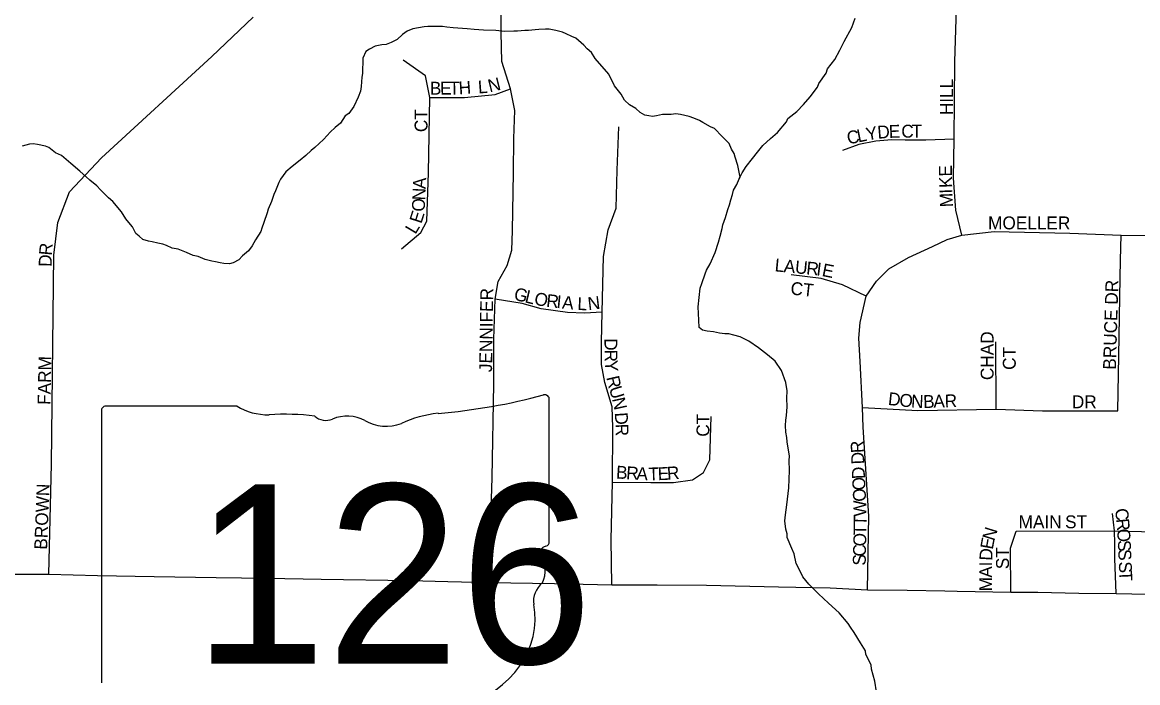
# Model space of a CAD drawing. Extents: x 0 to 34, y -2.3 to 22.
# Drawn here: x 4.399 to 5.22, y 14.899 to 15.385 of the extents above; entities that cross this region are included whole.
import ezdxf

# ---------------------------------------------------------------- set-up
doc = ezdxf.new("R2010")
doc.units = 0
for name, color, linetype in [('GM_X_Minor_River', 7, 'Continuous'), ('GM_X_State_Location', 7, 'Continuous'), ('GM_X_State_Route', 7, 'Continuous'), ('GM_X_State_Shield', 7, 'Continuous'), ('GM_X_Township_Subdivision', 7, 'Continuous'), ('GM_X_Township_Subdivision_Text', 7, 'Continuous')]:
    doc.layers.add(name, color=color, linetype=linetype)

msp = doc.modelspace()

# ---------------------------------------------------------------- linework, layer by layer
at = {"layer": 'GM_X_Minor_River'}
for p, q in [((5.00937, 15.38162), (5.01185, 15.38839)), ((4.67853, 15.37632), (4.67462, 15.37264)), ((4.68202, 15.37887), (4.67853, 15.37632)), ((4.68626, 15.38065), (4.68202, 15.37887)), ((4.69465, 15.38192), (4.68626, 15.38065)), ((4.69732, 15.38222), (4.69465, 15.38192)), ((4.70797, 15.38228), (4.69732, 15.38222)), ((4.71138, 15.3818), (4.70797, 15.38228)), ((4.71592, 15.38128), (4.71138, 15.3818)), ((4.72617, 15.3806), (4.71592, 15.38128)), ((4.73147, 15.38006), (4.72617, 15.3806)), ((4.7383, 15.37947), (4.73147, 15.38006)), ((4.74741, 15.3792), (4.7383, 15.37947)), ((4.75386, 15.37863), (4.74741, 15.3792)), ((4.7607, 15.3788), (4.75386, 15.37863)), ((4.76336, 15.37872), (4.7607, 15.3788)), ((4.7687, 15.37932), (4.76336, 15.37872)), ((4.77136, 15.37924), (4.7687, 15.37932)), ((4.77632, 15.37985), (4.77136, 15.37924)), ((4.77899, 15.38016), (4.77632, 15.37985)), ((4.78393, 15.38039), (4.77899, 15.38016)), ((4.78659, 15.38031), (4.78393, 15.38039)), ((4.79151, 15.3794), (4.78659, 15.38031)), ((4.79641, 15.37811), (4.79151, 15.3794)), ((4.79904, 15.3769), (4.79641, 15.37811)), ((4.80316, 15.37487), (4.79904, 15.3769)), ((5.00375, 15.37115), (5.00937, 15.38162)), ((4.66349, 15.36879), (4.65852, 15.3678)), ((4.66654, 15.36908), (4.66349, 15.36879)), ((4.67038, 15.37049), (4.66654, 15.36908)), ((4.67462, 15.37264), (4.67038, 15.37049)), ((4.80617, 15.37364), (4.80316, 15.37487)), ((4.8121, 15.36853), (4.80617, 15.37364)), ((4.81468, 15.36579), (4.8121, 15.36853)), ((5.00052, 15.36479), (5.00375, 15.37115)), ((4.65156, 15.36383), (4.64952, 15.35895)), ((4.65427, 15.36565), (4.65156, 15.36383)), ((4.65852, 15.3678), (4.65427, 15.36565)), ((4.81764, 15.36304), (4.81468, 15.36579)), ((4.82056, 15.35878), (4.81764, 15.36304)), ((4.99691, 15.35806), (5.00052, 15.36479)), ((4.64952, 15.35895), (4.64919, 15.34756)), ((4.83049, 15.34708), (4.82056, 15.35878)), ((4.99138, 15.35101), (4.99691, 15.35806)), ((4.64873, 15.34492), (4.64816, 15.3381)), ((4.64919, 15.34756), (4.64873, 15.34492)), ((4.8348, 15.3386), (4.83049, 15.34708)), ((4.98499, 15.34018), (4.99053, 15.348)), ((4.99053, 15.348), (4.99138, 15.35101)), ((4.64816, 15.3381), (4.64768, 15.33469)), ((4.83956, 15.33237), (4.8348, 15.3386)), ((4.97863, 15.3305), (4.98415, 15.33755)), ((4.98415, 15.33755), (4.98499, 15.34018)), ((4.64603, 15.33018), (4.64279, 15.32344)), ((4.64768, 15.33469), (4.64603, 15.33018)), ((4.8421, 15.32812), (4.83956, 15.33237)), ((4.8458, 15.32459), (4.8421, 15.32812)), ((4.9739, 15.32494), (4.97863, 15.3305)), ((4.64279, 15.32344), (4.63922, 15.31823)), ((4.85028, 15.3218), (4.8458, 15.32459)), ((4.85362, 15.31904), (4.85028, 15.3218)), ((4.85699, 15.31704), (4.85362, 15.31904)), ((4.9622, 15.31465), (4.96881, 15.31977)), ((4.96881, 15.31977), (4.9739, 15.32494)), ((4.63294, 15.3112), (4.62904, 15.30789)), ((4.63651, 15.31641), (4.63294, 15.3112)), ((4.63922, 15.31823), (4.63651, 15.31641)), ((4.86001, 15.31657), (4.85699, 15.31704)), ((4.86266, 15.31611), (4.86001, 15.31657)), ((4.86571, 15.3164), (4.86266, 15.31611)), ((4.86992, 15.31741), (4.86571, 15.3164)), ((4.87639, 15.3176), (4.86992, 15.31741)), ((4.87982, 15.31787), (4.87639, 15.3176)), ((4.88322, 15.31739), (4.87982, 15.31787)), ((4.88964, 15.31606), (4.88322, 15.31739)), ((4.89303, 15.31482), (4.88964, 15.31606)), ((4.89717, 15.31317), (4.89303, 15.31482)), ((4.89978, 15.31158), (4.89717, 15.31317)), ((4.90539, 15.30837), (4.89978, 15.31158)), ((4.95468, 15.30424), (4.96137, 15.31202)), ((4.96137, 15.31202), (4.9622, 15.31465)), ((4.62552, 15.30458), (4.62317, 15.30199)), ((4.62904, 15.30789), (4.62552, 15.30458)), ((4.90839, 15.30714), (4.90539, 15.30837)), ((4.91393, 15.30128), (4.90839, 15.30714)), ((4.94961, 15.29983), (4.95468, 15.30424)), ((4.40404, 15.29562), (4.39868, 15.29426)), ((4.40671, 15.29592), (4.40404, 15.29562)), ((4.41012, 15.29544), (4.40671, 15.29592)), ((4.41578, 15.29413), (4.41012, 15.29544)), ((4.41842, 15.29329), (4.41578, 15.29413)), ((4.62042, 15.29903), (4.61417, 15.29314)), ((4.62317, 15.30199), (4.62042, 15.29903)), ((4.9191, 15.29618), (4.91393, 15.30128)), ((4.92088, 15.29195), (4.9191, 15.29618)), ((4.93982, 15.28987), (4.94376, 15.29469)), ((4.94376, 15.29469), (4.94961, 15.29983)), ((4.42325, 15.28935), (4.41842, 15.29329)), ((4.42775, 15.28732), (4.42325, 15.28935)), ((4.43442, 15.28142), (4.42775, 15.28732)), ((4.60754, 15.28726), (4.60326, 15.28397)), ((4.61145, 15.29094), (4.60754, 15.28726)), ((4.61417, 15.29314), (4.61145, 15.29094)), ((4.92269, 15.28886), (4.92088, 15.29195)), ((4.92337, 15.28618), (4.92269, 15.28886)), ((4.92548, 15.28004), (4.92337, 15.28618)), ((4.93626, 15.28503), (4.93982, 15.28987)), ((4.44111, 15.2759), (4.43442, 15.28142)), ((4.59742, 15.27921), (4.59275, 15.27517)), ((4.60326, 15.28397), (4.59742, 15.27921)), ((4.92613, 15.27622), (4.92548, 15.28004)), ((4.92874, 15.27462), (4.93153, 15.2791)), ((4.93153, 15.2791), (4.93626, 15.28503)), ((4.44592, 15.27158), (4.44111, 15.2759)), ((4.44851, 15.26922), (4.44592, 15.27158)), ((4.58879, 15.26997), (4.58758, 15.26734)), ((4.59275, 15.27517), (4.58879, 15.26997)), ((4.92469, 15.266), (4.92633, 15.27013)), ((4.92712, 15.27125), (4.92613, 15.27622)), ((4.92633, 15.27013), (4.92874, 15.27462)), ((4.92633, 15.27013), (4.92712, 15.27125)), ((4.45371, 15.26489), (4.44851, 15.26922)), ((4.45629, 15.26215), (4.45371, 15.26489)), ((4.46221, 15.25627), (4.45629, 15.26215)), ((4.58512, 15.26134), (4.58391, 15.25871)), ((4.58758, 15.26734), (4.58512, 15.26134)), ((4.92143, 15.2585), (4.92229, 15.2619)), ((4.92229, 15.2619), (4.92469, 15.266)), ((4.46555, 15.25351), (4.46221, 15.25627)), ((4.47178, 15.24573), (4.46555, 15.25351)), ((4.58224, 15.25345), (4.57979, 15.24782)), ((4.58391, 15.25871), (4.58224, 15.25345)), ((4.91932, 15.25097), (4.92018, 15.25474)), ((4.92018, 15.25474), (4.92143, 15.2585)), ((4.47506, 15.24069), (4.47178, 15.24573)), ((4.57896, 15.24519), (4.57647, 15.23804)), ((4.57979, 15.24782), (4.57896, 15.24519)), ((4.91638, 15.24156), (4.91808, 15.24759)), ((4.91808, 15.24759), (4.91932, 15.25097)), ((4.47726, 15.23797), (4.47506, 15.24069)), ((4.47983, 15.23485), (4.47726, 15.23797)), ((4.57647, 15.23804), (4.57521, 15.2339)), ((4.91433, 15.2363), (4.91638, 15.24156)), ((4.48235, 15.22984), (4.47983, 15.23485)), ((4.48495, 15.22786), (4.48235, 15.22984)), ((4.57437, 15.23127), (4.5704, 15.22531)), ((4.57521, 15.2339), (4.57437, 15.23127)), ((4.91257, 15.228), (4.91387, 15.23365)), ((4.91387, 15.23365), (4.91433, 15.2363)), ((4.48754, 15.2255), (4.48495, 15.22786)), ((4.49169, 15.22424), (4.48754, 15.2255)), ((4.49434, 15.22378), (4.49169, 15.22424)), ((4.49849, 15.2229), (4.49434, 15.22378)), ((4.50227, 15.22203), (4.49849, 15.2229)), ((4.5049, 15.22119), (4.50227, 15.22203)), ((4.50903, 15.21916), (4.5049, 15.22119)), ((4.56799, 15.22082), (4.56522, 15.2171)), ((4.5704, 15.22531), (4.56799, 15.22082)), ((4.9088, 15.21595), (4.9113, 15.22347)), ((4.9113, 15.22347), (4.91257, 15.228)), ((4.51356, 15.21827), (4.50903, 15.21916)), ((4.51957, 15.21581), (4.51356, 15.21827)), ((4.52445, 15.21376), (4.51957, 15.21581)), ((4.52823, 15.21289), (4.52445, 15.21376)), ((4.53349, 15.21083), (4.52823, 15.21289)), ((4.56094, 15.21343), (4.55819, 15.21048)), ((4.56522, 15.2171), (4.56094, 15.21343)), ((4.90514, 15.2077), (4.9088, 15.21595)), ((4.5384, 15.20955), (4.53349, 15.21083)), ((4.54104, 15.20909), (4.5384, 15.20955)), ((4.54444, 15.20823), (4.54104, 15.20909)), ((4.54709, 15.20777), (4.54444, 15.20823)), ((4.55127, 15.20764), (4.54709, 15.20777)), ((4.55395, 15.20832), (4.55127, 15.20764)), ((4.55819, 15.21048), (4.55395, 15.20832)), ((4.90234, 15.20285), (4.90514, 15.2077)), ((4.89902, 15.19307), (4.90151, 15.20021)), ((4.90151, 15.20021), (4.90234, 15.20285)), ((4.89625, 15.17605), (4.89778, 15.18968)), ((4.89778, 15.18968), (4.89902, 15.19307)), ((4.89672, 15.16616), (4.89625, 15.17605)), ((4.89695, 15.16084), (4.89672, 15.16616)), ((4.89955, 15.15886), (4.89695, 15.16084)), ((4.90295, 15.158), (4.89955, 15.15886)), ((4.9075, 15.15748), (4.90295, 15.158)), ((4.91203, 15.15659), (4.9075, 15.15748)), ((4.91582, 15.15609), (4.91203, 15.15659)), ((4.91886, 15.156), (4.91582, 15.15609)), ((4.92263, 15.15513), (4.91886, 15.156)), ((4.92716, 15.15385), (4.92263, 15.15513)), ((4.93353, 15.15063), (4.92716, 15.15385)), ((4.94061, 15.14585), (4.93353, 15.15063)), ((4.9473, 15.14071), (4.94061, 15.14585)), ((4.95287, 15.13599), (4.9473, 15.14071)), ((4.95761, 15.12901), (4.95287, 15.13599)), ((4.96077, 15.12018), (4.95761, 15.12901)), ((4.96174, 15.11407), (4.96077, 15.12018)), ((4.96159, 15.10875), (4.96174, 15.11407)), ((4.96178, 15.10229), (4.96159, 15.10875)), ((4.96121, 15.09585), (4.96178, 15.10229)), ((4.96063, 15.08865), (4.96074, 15.09244)), ((4.96074, 15.09244), (4.96121, 15.09585)), ((4.96086, 15.0837), (4.96063, 15.08865)), ((4.96151, 15.07988), (4.96086, 15.0837)), ((4.96179, 15.07646), (4.96151, 15.07988)), ((4.9634, 15.06615), (4.96179, 15.07646)), ((4.9633, 15.06273), (4.9634, 15.06615)), ((4.96347, 15.05551), (4.9633, 15.06273)), ((4.9631, 15.0426), (4.96347, 15.05551)), ((4.9621, 15.03427), (4.9631, 15.0426)), ((4.9616, 15.03011), (4.9621, 15.03427)), ((4.96063, 15.02292), (4.9616, 15.03011)), ((4.96012, 15.01838), (4.96063, 15.02292)), ((4.96071, 15.01228), (4.96012, 15.01838)), ((4.96175, 15.00883), (4.96071, 15.01228)), ((4.96167, 15.00617), (4.96175, 15.00883)), ((4.96524, 14.99809), (4.96167, 15.00617)), ((4.96703, 14.99424), (4.96524, 14.99809)), ((4.96834, 14.98698), (4.96703, 14.99424)), ((4.97086, 14.98234), (4.96834, 14.98698)), ((4.97338, 14.97733), (4.97086, 14.98234)), ((4.97778, 14.97188), (4.97338, 14.97733)), ((4.9848, 14.96483), (4.97778, 14.97188)), ((4.9922, 14.95777), (4.9848, 14.96483)), ((4.99998, 14.9507), (4.9922, 14.95777)), ((5.0066, 14.9429), (4.99998, 14.9507)), ((5.00842, 14.94019), (5.0066, 14.9429)), ((5.01097, 14.93631), (5.00842, 14.94019)), ((5.01569, 14.92857), (5.01097, 14.93631)), ((5.01932, 14.92277), (5.01569, 14.92857)), ((5.01962, 14.9201), (5.01932, 14.92277)), ((5.02358, 14.91238), (5.01962, 14.9201)), ((5.02388, 14.90933), (5.02358, 14.91238)), ((5.02628, 14.90052), (5.02388, 14.90933)), ((5.02757, 14.89251), (5.02628, 14.90052))]:
    msp.add_line(p, q, dxfattribs=at)
at = {"layer": 'GM_X_State_Route'}
for p, q in [((4.37638, 14.97924), (4.41835, 14.97924)), ((4.41835, 14.97924), (4.45408, 14.97808)), ((4.45408, 14.97808), (4.49589, 14.97758)), ((4.49589, 14.97758), (4.54158, 14.97668)), ((4.54158, 14.97668), (4.57872, 14.97629)), ((4.57872, 14.97629), (4.61874, 14.9756)), ((4.61874, 14.9756), (4.68439, 14.9746)), ((4.68439, 14.9746), (4.71191, 14.97381)), ((4.71191, 14.97381), (4.7421, 14.97301)), ((4.7421, 14.97301), (4.79056, 14.97232)), ((4.79056, 14.97232), (4.83277, 14.97142)), ((4.83277, 14.97142), (4.86614, 14.97142)), ((4.86614, 14.97142), (4.90249, 14.97102)), ((4.90249, 14.97102), (4.95533, 14.96984)), ((4.95533, 14.96984), (4.99346, 14.96924)), ((4.99346, 14.96924), (5.02088, 14.96765)), ((5.02088, 14.96765), (5.05007, 14.96737)), ((5.05007, 14.96737), (5.07778, 14.96689)), ((5.07778, 14.96689), (5.08696, 14.96674)), ((5.08696, 14.96674), (5.12638, 14.96584)), ((5.12638, 14.96584), (5.14634, 14.96603)), ((5.14634, 14.96603), (5.1764, 14.96522)), ((5.1764, 14.96522), (5.20381, 14.96496)), ((5.20381, 14.96496), (5.24073, 14.96426))]:
    msp.add_line(p, q, dxfattribs=at)
at = {"layer": 'GM_X_State_Shield'}
for p, q in [((4.78666, 15.00315), (4.78666, 15.10784)), ((4.45708, 15.09944), (4.45708, 14.89932)), ((4.55684, 15.10288), (4.46032, 15.10288)), ((4.78663, 15.00318), (4.78666, 15.00315))]:
    msp.add_line(p, q, dxfattribs=at)
for centre, major_axis, start_param, end_param in [((4.66926, 15.37571), (0.34952, 0), 4.814394, 5.042369), ((4.78301, 15.10827), (0.00367, 0), 6.141152, 7.989035), ((4.46085, 15.09986), (0.00382, 0), 1.712693, 3.28349), ((4.57983, 15.12611), (0.03703, 0), 4.042523, 4.731795), ((4.59211, 14.99053), (0.13295, 0), 1.404758, 1.657858), ((4.71384, 15.04176), (0.07032, 0), 1.699011, 2.107814), ((4.62229, 15.1009), (0.01068, 0), 3.836095, 5.185415), ((4.63798, 15.07777), (0.02221, 0), 0.950623, 2.079405), ((4.66665, 15.10949), (0.02672, 0), 4.081561, 5.145723), ((4.78581, 14.99547), (0.00568, 0), 1.883978, 3.671073), ((4.78275, 15.00275), (0.00393, 0), 5.05454, 6.418171), ((4.74969, 14.98224), (0.03409, 0), 5.934695, 6.695948), ((4.79981, 14.95934), (0.0248, 0), 2.387724, 3.262537), ((4.68884, 14.94603), (0.08742, 0), 5.101752, 6.440018)]:
    msp.add_ellipse(centre, major_axis=major_axis, ratio=0.8, start_param=start_param, end_param=end_param, dxfattribs=at)
at = {"layer": 'GM_X_Township_Subdivision'}
for p, q in [((4.75137, 15.37776), (4.75152, 15.42061)), ((5.08521, 15.35629), (5.08657, 15.40379)), ((4.53826, 15.36006), (4.56871, 15.38911)), ((4.75165, 15.35641), (4.75137, 15.37776)), ((4.45702, 15.28559), (4.53826, 15.36006)), ((4.69564, 15.34585), (4.67923, 15.35742)), ((4.75822, 15.33626), (4.75165, 15.35641)), ((5.08458, 15.29926), (5.08521, 15.35629)), ((4.69884, 15.33001), (4.69564, 15.34585)), ((4.74673, 15.33219), (4.75822, 15.33626)), ((4.76142, 15.32041), (4.75822, 15.33626)), ((4.69766, 15.27443), (4.69884, 15.33001)), ((4.69884, 15.33001), (4.72427, 15.33)), ((4.72427, 15.33), (4.74673, 15.33219)), ((4.76059, 15.29975), (4.76142, 15.32041)), ((4.83671, 15.27653), (4.83794, 15.30838)), ((4.76031, 15.27477), (4.76059, 15.29975)), ((5.01441, 15.29529), (5.0024, 15.29105)), ((5.02699, 15.29798), (5.01441, 15.29529)), ((5.03871, 15.29883), (5.02699, 15.29798)), ((5.04861, 15.29854), (5.03871, 15.29883)), ((5.06387, 15.29868), (5.04861, 15.29854)), ((5.08458, 15.29926), (5.06387, 15.29868)), ((5.08426, 15.27075), (5.08458, 15.29926)), ((4.43356, 15.26066), (4.45702, 15.28559)), ((4.69648, 15.23888), (4.69766, 15.27443)), ((4.75961, 15.23192), (4.76031, 15.27477)), ((4.83598, 15.24863), (4.83671, 15.27653)), ((5.08586, 15.24712), (5.08426, 15.27075)), ((4.42486, 15.23798), (4.43356, 15.26066)), ((4.82998, 15.23258), (4.83598, 15.24863)), ((5.09022, 15.22876), (5.08586, 15.24712)), ((4.42211, 15.21408), (4.42486, 15.23798)), ((4.6921, 15.23062), (4.69648, 15.23888)), ((4.67795, 15.21867), (4.6921, 15.23062)), ((4.75906, 15.21755), (4.75961, 15.23192)), ((4.82646, 15.21298), (4.82998, 15.23258)), ((5.07956, 15.22544), (5.09022, 15.22876)), ((5.09022, 15.22876), (5.11409, 15.23138)), ((5.11409, 15.23138), (5.16981, 15.23013)), ((5.16981, 15.23013), (5.20767, 15.22878)), ((5.20714, 15.2103), (5.20767, 15.22878)), ((5.20767, 15.22878), (5.26186, 15.22803)), ((5.05109, 15.21229), (5.06861, 15.22043)), ((5.06861, 15.22043), (5.07956, 15.22544)), ((4.42021, 15.06006), (4.42211, 15.21408)), ((4.75571, 15.20639), (4.75906, 15.21755)), ((4.8255, 15.17198), (4.82646, 15.21298)), ((5.03668, 15.20394), (5.05109, 15.21229)), ((4.74914, 15.19466), (4.75571, 15.20639)), ((5.0275, 15.19485), (5.03668, 15.20394)), ((5.20676, 15.19721), (5.20714, 15.2103)), ((4.98682, 15.19685), (4.96472, 15.19947)), ((5.00238, 15.19202), (4.98682, 15.19685)), ((5.20586, 15.13981), (5.20676, 15.19721)), ((4.74677, 15.18154), (4.74914, 15.19466)), ((5.01994, 15.18372), (5.00238, 15.19202)), ((5.01994, 15.18372), (5.0275, 15.19485)), ((4.74593, 15.15224), (4.74677, 15.18154)), ((4.76668, 15.17835), (4.74677, 15.18154)), ((5.01548, 15.16434), (5.01994, 15.18372)), ((4.78064, 15.17434), (4.76668, 15.17835)), ((4.80002, 15.17181), (4.78064, 15.17434)), ((4.81267, 15.17137), (4.80002, 15.17181)), ((4.8255, 15.17198), (4.81267, 15.17137)), ((4.82523, 15.15005), (4.8255, 15.17198)), ((5.01439, 15.15295), (5.01548, 15.16434)), ((4.74579, 15.11916), (4.74593, 15.15224)), ((4.82508, 15.13351), (4.82523, 15.15005)), ((5.01541, 15.13581), (5.01439, 15.15295)), ((5.11549, 15.1005), (5.11524, 15.15019)), ((5.20502, 15.09943), (5.20586, 15.13981)), ((4.82752, 15.12034), (4.82508, 15.13351)), ((5.01711, 15.10175), (5.01541, 15.13581)), ((4.74454, 15.05008), (4.74579, 15.11916)), ((4.83289, 15.10227), (4.82752, 15.12034)), ((4.8335, 15.08711), (4.83289, 15.10227)), ((5.01711, 15.10175), (5.05793, 15.09973)), ((5.01782, 15.08744), (5.01711, 15.10175)), ((5.05793, 15.09973), (5.11549, 15.1005)), ((5.11549, 15.1005), (5.14972, 15.09948)), ((5.14972, 15.09948), (5.20502, 15.09943)), ((4.90485, 15.06323), (4.90593, 15.09523)), ((4.83319, 15.047), (4.8335, 15.08711)), ((5.0218, 15.02176), (5.01782, 15.08744)), ((4.41835, 14.97924), (4.42021, 15.06006)), ((4.90011, 15.05389), (4.90485, 15.06323)), ((4.7421, 14.97301), (4.74454, 15.05008)), ((4.87821, 15.04669), (4.89199, 15.04853)), ((4.89199, 15.04853), (4.90011, 15.05389)), ((4.83212, 15.00443), (4.83319, 15.047)), ((4.83319, 15.047), (4.86136, 15.04654)), ((4.86136, 15.04654), (4.87821, 15.04669)), ((5.20271, 15.01096), (5.20129, 15.02392)), ((5.02088, 14.96765), (5.0218, 15.02176)), ((5.12617, 14.9983), (5.1304, 15.01078)), ((5.1304, 15.01078), (5.20271, 15.01096)), ((5.20271, 15.01096), (5.23258, 15.01039)), ((5.20286, 15.00185), (5.20271, 15.01096)), ((4.83277, 14.97142), (4.83212, 15.00443)), ((5.20303, 14.99069), (5.20286, 15.00185)), ((5.12638, 14.96584), (5.12617, 14.9983)), ((5.20381, 14.96496), (5.20303, 14.99069))]:
    msp.add_line(p, q, dxfattribs=at)

# ---------------------------------------------------------------- texts
at = {"layer": 'GM_X_State_Location'}
for s in ['s', 'r']:
    msp.add_text(s, height=0.000189, dxfattribs=at).set_placement((4.61816, 14.98607))
msp.add_text('126', height=0.000189, rotation=0.00001, dxfattribs=at).set_placement((4.55131, 14.97229))
at = {"layer": 'GM_X_State_Shield'}
msp.add_text('126', height=0.131836, dxfattribs=at).set_placement((4.52457, 14.91343))
at = {"layer": 'GM_X_Township_Subdivision_Text'}
for s, rotation, p in [('N', 13.67607, (4.74283, 15.33368)), ('HILL', 90, (5.08381, 15.31701)), ('B', 0.30357, (4.69882, 15.33209)), ('E', 0.30055, (4.70632, 15.33213)), ('T', 0.3021, (4.71299, 15.33216)), ('H', 4.04245, (4.72032, 15.33222)), ('L', 4.29341, (4.73454, 15.33292)), ('CT', 90, (4.69703, 15.30451)), ('C', 11.37899, (5.0067, 15.2954)), ('L', 11.3807, (5.01406, 15.29688)), ('Y', 9.94024, (5.02053, 15.29819)), ('D', 4.52904, (5.0285, 15.2996)), ('E', 1.50276, (5.03668, 15.30025)), ('C', 0.30357, (5.04579, 15.30044)), ('T', 0.25953, (5.05329, 15.30048)), ('E', 90.38252, (5.08302, 15.27184)), ('A', 87.21466, (4.69569, 15.26248)), ('K', 91.60117, (5.08325, 15.26357)), ('N', 87.20689, (4.69528, 15.25415)), ('I', 92.2631, (5.08342, 15.25943)), ('O', 88.26447, (4.69503, 15.24587)), ('M', 92.25896, (5.08381, 15.24944)), ('E', 72.38348, (4.69253, 15.2367)), ('MOELLER', 0.00001, (5.10964, 15.23296)), ('L', 59.18501, (4.68814, 15.22881)), ('R', 84.84404, (4.42049, 15.21345)), ('D', 89.03823, (4.42036, 15.2053)), ('L', 354.51369, (4.95231, 15.20212)), ('A', 354.50579, (4.95894, 15.20148)), ('U', 354.5159, (4.96724, 15.20068)), ('R', 354.50326, (4.97553, 15.19989)), ('I', 352.8777, (4.98293, 15.19918)), ('E', 348.87894, (4.98689, 15.19869)), ('JENNIFER', 89.10482, (4.74453, 15.1278)), ('G', 346.61181, (4.76006, 15.18124)), ('L', 346.59991, (4.76817, 15.17931)), ('CT', 353.65714, (4.96387, 15.18509)), ('BRUCE DR', 88.33984, (5.20369, 15.12956)), ('O', 349.06984, (4.77509, 15.17767)), ('R', 353.88985, (4.78413, 15.17596)), ('I', 354.29668, (4.79166, 15.17516)), ('A', 354.30174, (4.79581, 15.17474)), ('L', 357.86068, (4.80723, 15.17362)), ('N', 6.71282, (4.81549, 15.17344)), ('CHAD', 90, (5.11369, 15.12201)), ('D', 270.40981, (4.82726, 15.15282)), ('FARM', 88.83149, (4.41953, 15.10371)), ('R', 270.40683, (4.82732, 15.14449)), ('CT', 90, (5.12998, 15.12951)), ('Y', 274.13416, (4.8274, 15.13633)), ('R', 282.78816, (4.82862, 15.12403)), ('U', 286.90013, (4.83047, 15.11601)), ('N', 282.46954, (4.83284, 15.10823)), ('D', 353.75876, (5.03567, 15.10378)), ('O', 353.76255, (5.04396, 15.10287)), ('N', 356.65732, (5.05276, 15.10192)), ('B', 1.585, (5.06197, 15.10142)), ('A', 1.67752, (5.06949, 15.10163)), ('R', 1.69185, (5.07782, 15.10188)), ('DR', 0.00001, (5.17131, 15.10129)), ('D', 273.8279, (4.83484, 15.09798)), ('R', 271.46943, (4.83539, 15.08977)), ('CT', 90, (4.90452, 15.08034)), ('R', 92.59927, (5.01824, 15.06853)), ('D', 92.60832, (5.01862, 15.06021)), ('B', 356.37898, (4.83559, 15.04962)), ('R', 356.37898, (4.84308, 15.04915)), ('A', 356.65732, (4.85061, 15.04867)), ('T', 0.94308, (4.8597, 15.04817)), ('E', 2.66925, (4.86668, 15.04829)), ('R', 4.45943, (4.87366, 15.04862)), ('D', 92.60754, (5.01911, 15.04938)), ('O', 92.6053, (5.01949, 15.04106)), ('BROWN', 87.79755, (4.41703, 14.99708)), ('O', 92.60012, (5.01987, 15.03273)), ('W', 92.01752, (5.02025, 15.0218)), ('C', 275.94863, (5.20308, 15.0272)), ('T', 88.72933, (5.02003, 15.00788)), ('T', 89.26984, (5.02017, 15.01464)), ('MAIN', 0.00001, (5.13214, 15.01296)), ('ST', 0.00001, (5.16631, 15.01296)), ('R', 275.59461, (5.20385, 15.01975)), ('O', 88.72684, (5.01984, 14.99955)), ('N', 72.87183, (5.1142, 15.0032)), ('O', 273.43386, (5.20458, 15.01238)), ('C', 88.7248, (5.01967, 14.99205)), ('E', 79.7231, (5.11308, 14.99693)), ('ST', 90, (5.12498, 14.98284)), ('S', 272.63731, (5.20507, 15.0041)), ('S', 88.72938, (5.01953, 14.98538)), ('D', 86.57436, (5.11262, 14.98891)), ('S', 272.59637, (5.20538, 14.99744)), ('I', 90, (5.11263, 14.9849)), ('A', 90, (5.11263, 14.97656)), ('S', 272.60319, (5.2058, 14.98828)), ('M', 90, (5.11263, 14.96656)), ('T', 272.60348, (5.2061, 14.98162))]:
    msp.add_text(s, height=0.00947, rotation=rotation, dxfattribs=at).set_placement(p)

doc.saveas('drawing.dxf')
